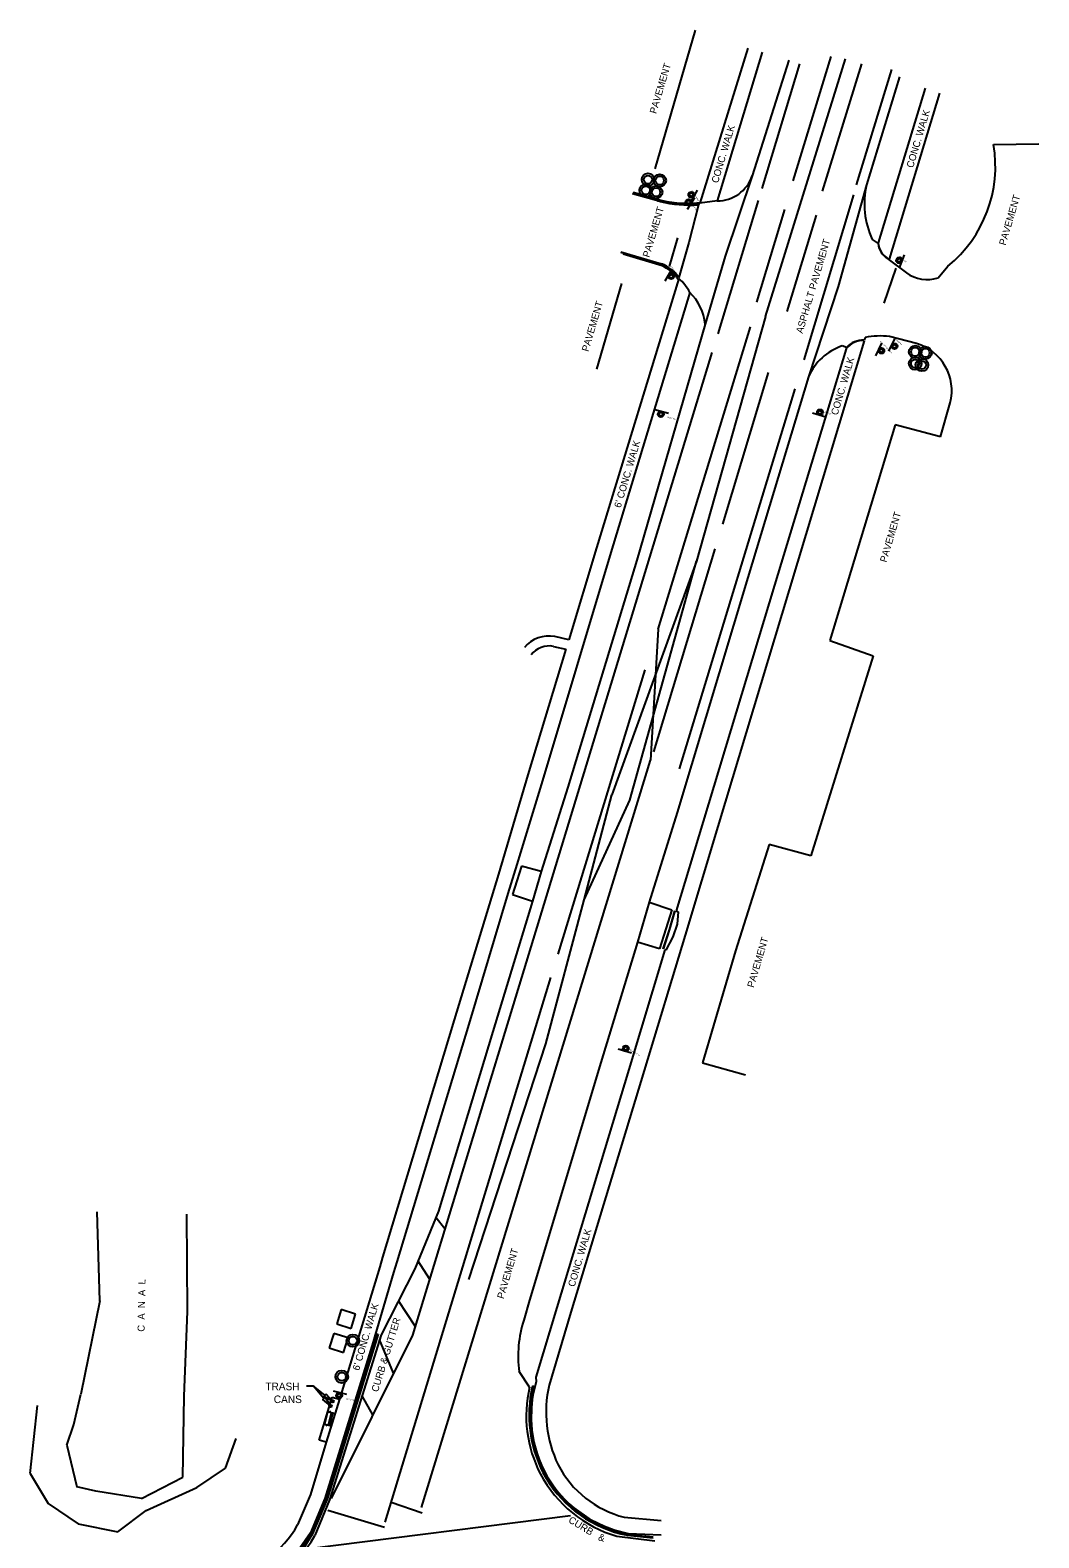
# Model space of a CAD drawing. Extents: x 925226 to 926411, y 852913 to 858733.
# Drawn here: x 925769 to 926169, y 858135 to 858733 of the extents above; entities that cross this region are included whole.
import ezdxf

# ---------------------------------------------------------------- set-up
doc = ezdxf.new("R2010")
doc.units = 0
for name, color, linetype in [('BankMent_ep', 7, 'Continuous'), ('BusStop_ep', 7, 'Continuous'), ('CGep_ep', 7, 'Continuous'), ('CGFace_ep', 7, 'Continuous'), ('CLConst_dp', 7, 'Continuous'), ('ConcSlabs_ep', 7, 'Continuous'), ('CurbRamp_ep', 7, 'Continuous'), ('EndTreat_ep', 7, 'Continuous'), ('ManholeSW_ep', 7, 'Continuous'), ('PavtAsphalt_ep', 7, 'Continuous'), ('PavtCrown_ep', 7, 'Continuous'), ('PavtMisc_ep', 7, 'Continuous'), ('SidewalkBack_ep', 7, 'Continuous'), ('SidewalkFront_ep', 7, 'Continuous'), ('TextLabel', 7, 'Continuous'), ('TextNotes', 7, 'Continuous'), ('Trash_ep', 7, 'Continuous'), ('WaterEdge_ep', 7, 'Continuous'), ('XSPt_ep', 7, 'Continuous')]:
    doc.layers.add(name, color=color, linetype=linetype)

# ---------------------------------------------------------------- blocks, each defined once
blk = doc.blocks.new('BNCH')
at = {"layer": 'BusStop_ep'}
for p, q in [((-2.5, 0), (2.5, 0)), ((-2.5, -0.5), (-2.5, -1.23)), ((2.5, -1.23), (2.5, -0.5))]:
    blk.add_line(p, q, dxfattribs=at)
blk.add_lwpolyline([(-2.5, -0.5), (2.5, -0.5), (2.5, 1.68), (-2.5, 1.68), (-2.5, 0), (-2.5, -0.5)], close=True, dxfattribs=at)
for centre, start, end in [((-3.55, 0), 0.23588, 69.15443), ((3.55, 0), 110.84558, 179.76412)]:
    blk.add_arc(centre, 1.05, start, end, dxfattribs=at)
blk = doc.blocks.new('SSS')
at = {"layer": 'ManholeSW_ep'}
blk.add_line((-2.77, 1.15), (2.77, 1.15), dxfattribs=at)
for radius in [1.15, 0.692]:
    blk.add_circle((0, 0), radius, dxfattribs=at)
blk = doc.blocks.new('BOL')
at = {"layer": 'TextNotes'}
for radius in [2.5, 1.67]:
    blk.add_circle((0, 0), radius, dxfattribs=at)

msp = doc.modelspace()

# ---------------------------------------------------------------- linework, layer by layer
at = {"layer": 'BankMent_ep'}
for p, q in [((925768.95, 858160.47), (925771.85, 858187.46)), ((925846.44, 858162.53), (925850.59, 858174.27)), ((925835.09, 858154.86), (925846.44, 858162.53)), ((925768.95, 858160.47), (925776.1, 858148.55)), ((925814.99, 858145.82), (925835.09, 858154.86)), ((925776.1, 858148.55), (925787.96, 858140.47)), ((925803.77, 858137.35), (925814.99, 858145.82)), ((925787.96, 858140.47), (925803.77, 858137.35))]:
    msp.add_line(p, q, dxfattribs=at)
at = {"layer": 'CGep_ep'}
for p, q in [((926024.35, 858383.59), (926022.22, 858375.97)), ((926022.22, 858375.97), (926019.83, 858368.44)), ((925906.86, 858215.73), (925886.63, 858150.3)), ((925886.63, 858150.3), (925880.88, 858136.47)), ((925880.88, 858136.47), (925877.28, 858130.67)), ((926003.07, 858136.54), (926005.77, 858136)), ((926005.77, 858136), (926015.98, 858134.99))]:
    msp.add_line(p, q, dxfattribs=at)
for centre, major_axis, ratio, start_param, end_param in [((926016.84, 858183.64), (-13.65, -48.2), 0.999607, 4.763001, 5.460335), ((926014.98, 858183.35), (-4.42, -48.1), 0.999813, 5.288393, 6.125776)]:
    msp.add_ellipse(centre, major_axis=major_axis, ratio=ratio, start_param=start_param, end_param=end_param, dxfattribs=at)
at = {"layer": 'CGFace_ep'}
for p, q in [((926017.66, 858665.05), (926007.77, 858667.92)), ((926033.98, 858663.72), (926033.27, 858663.71)), ((926033.98, 858663.72), (926034.34, 858664.12)), ((926003.18, 858644.71), (926019.63, 858639.83)), ((926022.42, 858375.91), (926024.72, 858383.54)), ((926020.05, 858368.38), (926022.42, 858375.91)), ((925905.43, 858212.32), (925886.23, 858150.33)), ((925906.51, 858215.66), (925905.43, 858212.32)), ((925968.46, 858195.01), (925967.93, 858192.55)), ((925886.23, 858150.33), (925880.51, 858136.71)), ((925880.51, 858136.71), (925876.45, 858130.76)), ((926015.89, 858135.26), (926005.79, 858136.12))]:
    msp.add_line(p, q, dxfattribs=at)
for centre, major_axis, ratio, start_param, end_param in [((926029.76, 858716.5), (53.9, -7.88), 0.969953, 4.629197, 4.91788), ((926013.51, 858626.08), (-14.74, 4.01), 0.984765, 4.006354, 4.561623), ((926017.13, 858183.61), (-12.56, -48.42), 0.999645, 4.786285, 5.43341), ((926015.97, 858183.98), (-38.66, -30.36), 0.999885, 6.102191, 6.664596)]:
    msp.add_ellipse(centre, major_axis=major_axis, ratio=ratio, start_param=start_param, end_param=end_param, dxfattribs=at)
at = {"layer": 'ConcSlabs_ep'}
for p, q in [((925892.24, 858225.45), (925890.52, 858219.79)), ((925897.94, 858223.61), (925892.24, 858225.45)), ((925896.16, 858217.89), (925897.94, 858223.61)), ((925889.35, 858215.97), (925887.52, 858210.25)), ((925895.06, 858214.17), (925889.35, 858215.97)), ((925890.52, 858219.79), (925896.16, 858217.89)), ((925887.52, 858210.25), (925893.21, 858208.4)), ((925893.21, 858208.4), (925895.06, 858214.17)), ((925883.48, 858173.69), (925888.66, 858190.76)), ((925888.66, 858190.76), (925891.54, 858189.9)), ((925886.3, 858172.87), (925883.48, 858173.69))]:
    msp.add_line(p, q, dxfattribs=at)
at = {"layer": 'CurbRamp_ep'}
for p, q in [((925996.42, 858138.84), (925991.39, 858141.41)), ((925996.6, 858139.38), (925991.41, 858141.95)), ((926000.34, 858137.37), (925996.42, 858138.84)), ((926000.43, 858137.97), (925996.6, 858139.38)), ((926005.79, 858136.12), (926000.34, 858137.37)), ((926006.1, 858136.53), (926000.43, 858137.97))]:
    msp.add_line(p, q, dxfattribs=at)
at = {"layer": 'EndTreat_ep'}
for p, q in [((926073.91, 858719.32), (926059.01, 858669.89)), ((926086.39, 858722.22), (926071.36, 858672.96)), ((926098.59, 858719.41), (926082.93, 858668.86)), ((926110.43, 858717.15), (926096.45, 858671.42)), ((926057.59, 858665.19), (926041.51, 858612.34)), ((926095.3, 858667.36), (926075.66, 858602.06)), ((926068.04, 858661.6), (926056.94, 858624.86)), ((926080.58, 858659.36), (926068.89, 858621.19)), ((926025.57, 858650.34), (926022.34, 858638.98)), ((926107.51, 858624.48), (926112.23, 858638.41)), ((926017.97, 858495.22), (926054.48, 858615.07)), ((926039.17, 858604.9), (925964.66, 858360.2)), ((926061.57, 858597.03), (926043.39, 858536.8)), ((926072.12, 858590.54), (926026.29, 858439.78)), ((926040.38, 858527.03), (926016.1, 858446.56)), ((926017.97, 858495.22), (926014.82, 858443.32)), ((926012.57, 858479.05), (925978.18, 858366.38)), ((925924.04, 858146.9), (926014.82, 858443.32)), ((925964.66, 858360.2), (925920.52, 858215.34)), ((925975.27, 858357.15), (925909.61, 858141.17)), ((925933.34, 858257.42), (925929.81, 858261.98)), ((925927.31, 858237.63), (925922.72, 858244.64)), ((925921.61, 858218.9), (925915, 858228.94)), ((925920.52, 858215.34), (925888.32, 858150.52)), ((925913.04, 858200.27), (925907.48, 858213.57)), ((925904.84, 858183.76), (925900.54, 858191.28)), ((925909.4, 858139.01), (925886.92, 858145.75)), ((925924.38, 858144.73), (925912.02, 858148.94)), ((925983.15, 858143.63), (925878.67, 858130.44))]:
    msp.add_line(p, q, dxfattribs=at)
at = {"layer": 'PavtAsphalt_ep'}
for p, q in [((926069.74, 858720.84), (926055.16, 858674.97)), ((926113.62, 858714.18), (926100.47, 858671.42)), ((926055.16, 858674.97), (926044.44, 858643.13)), ((926100.47, 858671.42), (926089.3, 858631.05)), ((926044.44, 858643.13), (926036.53, 858616.14)), ((926089.3, 858631.05), (926077.51, 858595.26)), ((926036.53, 858616.14), (926009.45, 858522.57)), ((926077.51, 858595.26), (926053.51, 858515.65)), ((926009.45, 858522.57), (925982.12, 858432.5)), ((926053.51, 858515.65), (926025.43, 858422.5)), ((925982.12, 858432.5), (925971.51, 858399.12)), ((926025.43, 858422.5), (926014.41, 858386.99)), ((925971.51, 858399.12), (925968.06, 858387.43)), ((925968.06, 858387.43), (925952.43, 858335.69)), ((926014.41, 858386.99), (926009.67, 858371.17)), ((926009.67, 858371.17), (925995.14, 858323.42)), ((925952.43, 858335.69), (925930.82, 858264.45)), ((925995.14, 858323.42), (925966.94, 858229.14)), ((925930.82, 858264.45), (925921.46, 858241.53)), ((925921.46, 858241.53), (925908.05, 858215.38)), ((925966.94, 858229.14), (925964.65, 858221.24)), ((925908.05, 858215.38), (925887.68, 858149.96)), ((925966.91, 858194.65), (925962.78, 858200.84)), ((925887.68, 858149.96), (925881.84, 858135.81)), ((926001.59, 858135.59), (926016.58, 858133.78))]:
    msp.add_line(p, q, dxfattribs=at)
for centre, major_axis, ratio, start_param, end_param in [((926009.4, 858206.86), (-9.08, -46.17), 0.998912, 4.5957, 5.034579), ((926015.56, 858183.31), (-12.34, -48.43), 0.999593, 4.732875, 5.442276), ((926015.54, 858183.76), (32.89, 37.87), 0.999869, 2.774585, 3.574821), ((925840.63, 858159.33), (46.88, 7.33), 0.999985, 4.643805, 5.609384)]:
    msp.add_ellipse(centre, major_axis=major_axis, ratio=ratio, start_param=start_param, end_param=end_param, dxfattribs=at)
at = {"layer": 'PavtCrown_ep'}
for p, q in [((926060.53, 858619.22), (926092.17, 858721.3)), ((926060.53, 858619.22), (926033.16, 858522.15)), ((926033.16, 858522.15), (925999.61, 858429.51)), ((926006.74, 858427.41), (926033.16, 858522.15)), ((925988.53, 858387.92), (925999.61, 858429.51)), ((925988.53, 858387.92), (926006.74, 858427.41)), ((925973.39, 858330.74), (925988.53, 858387.92)), ((925942.86, 858237.31), (925973.39, 858330.74))]:
    msp.add_line(p, q, dxfattribs=at)
at = {"layer": 'PavtMisc_ep'}
for p, q in [((926032.58, 858732.72), (926016.61, 858677.78)), ((926150.9, 858687.32), (926168.83, 858687.67)), ((926018.68, 858664.72), (926007.71, 858667.8)), ((926041.33, 858664.98), (926034.47, 858664.17)), ((926033.88, 858663.46), (926030.03, 858648.52)), ((926034.47, 858664.17), (926033.88, 858663.46)), ((926030.03, 858648.52), (926026.14, 858634.58)), ((926102.81, 858649.73), (926105.09, 858648.06)), ((926003.1, 858644.85), (926019.2, 858640.09)), ((926109.12, 858641.92), (926116.31, 858636.49)), ((926128.86, 858634.49), (926132.8, 858639.15)), ((926003.44, 858632.2), (925993.49, 858598.28)), ((926100.01, 858610.83), (926099.53, 858609.77)), ((926120.35, 858608.5), (926109.61, 858611.21)), ((926092.55, 858606.92), (926090.88, 858607.54)), ((926129.78, 858571.52), (926133.74, 858584.94)), ((926111.88, 858576.2), (926085.96, 858490.66)), ((926129.78, 858571.52), (926111.88, 858576.2)), ((926085.96, 858490.66), (926103.11, 858484.62)), ((926103.11, 858484.62), (926078.43, 858405.36)), ((926061.87, 858409.87), (926048.55, 858367.62)), ((926078.43, 858405.36), (926061.87, 858409.87)), ((925963.7, 858401.3), (925961.94, 858395.46)), ((925971.51, 858399.12), (925963.7, 858401.3)), ((925961.94, 858395.46), (925960.2, 858390)), ((925960.2, 858390), (925968.06, 858387.43)), ((926014.41, 858386.99), (926023.3, 858383.89)), ((926023.3, 858383.89), (926021.01, 858376.36)), ((926021.01, 858376.36), (926018.44, 858368.45)), ((926018.44, 858368.45), (926009.67, 858371.17)), ((926048.55, 858367.62), (926035.52, 858323.32)), ((926035.52, 858323.32), (926052.52, 858318.49))]:
    msp.add_line(p, q, dxfattribs=at)
for centre, major_axis, ratio, start_param, end_param in [((926100.59, 858678.73), (21.68, 46.23), 0.999043, 4.2635, 5.319649), ((926041.31, 858679.59), (-6.93, -12.86), 0.999654, 0.495606, 1.74275), ((926133.68, 858664.04), (-1.45, -34.02), 0.999265, 4.536192, 5.18855), ((926030.11, 858713.2), (50.89, -7.76), 0.967364, 4.634829, 4.932324), ((926113.15, 858648.94), (-5.43, 6.06), 0.994499, 0.950964, 1.888021), ((926013.96, 858626.35), (-2.51, -14.49), 0.999582, 2.336296, 2.948722), ((926124.6, 858648.32), (-12.26, 7.71), 0.997119, 1.521594, 2.430162), ((926014.87, 858620.93), (16.59, 5.22), 0.999644, 0.157336, 0.565845), ((926016.86, 858614.33), (-2.74, 19.58), 0.998961, 4.66553, 5.386333), ((926105.93, 858584.16), (-27.16, 4.18), 0.993258, 4.729873, 5.081436), ((926098, 858586.35), (-13.63, -17.74), 0.998508, 4.121326, 4.956707), ((926099.05, 858601.02), (8.58, 2.08), 0.991412, 1.279937, 2.162751), ((926114.63, 858589.66), (11.3, 16.12), 0.999648, 5.081373, 6.600063)]:
    msp.add_ellipse(centre, major_axis=major_axis, ratio=ratio, start_param=start_param, end_param=end_param, dxfattribs=at)
at = {"layer": 'SidewalkBack_ep'}
for p, q in [((926053.43, 858725.58), (926034.47, 858664.17)), ((926129.5, 858707.7), (926109.45, 858641.89)), ((926026.08, 858634.23), (925993.48, 858527.46)), ((926099.64, 858609.58), (926069.79, 858510.82)), ((925993.48, 858527.46), (925982.5, 858490.95)), ((926069.79, 858510.82), (926041.56, 858416.99)), ((925982.5, 858490.95), (925976.91, 858492.28)), ((925981.34, 858487.24), (925966.22, 858437.44)), ((925966.22, 858437.44), (925954.57, 858398.11)), ((926041.56, 858416.99), (926028.65, 858373.82)), ((925954.57, 858398.11), (925937.02, 858340.3)), ((926028.65, 858373.82), (926012.34, 858320.26)), ((925937.02, 858340.3), (925910.33, 858251.85)), ((926012.34, 858320.26), (925983.35, 858224.35)), ((925910.33, 858251.85), (925908.64, 858246.2)), ((925908.64, 858246.2), (925907.52, 858242.41)), ((925907.52, 858242.41), (925891.54, 858189.9)), ((925983.35, 858224.35), (925974.66, 858195.48)), ((925891.54, 858189.9), (925886.3, 858172.87)), ((925886.3, 858172.87), (925880.07, 858152.1)), ((925880.07, 858152.1), (925874.97, 858140.08)), ((926004.45, 858143.1), (926019.08, 858141.77))]:
    msp.add_line(p, q, dxfattribs=at)
for centre, major_axis, ratio, start_param, end_param in [((925974.5, 858480.01), (6.88, 10.45), 0.996548, 0.388905, 1.465009), ((926022.1, 858184.86), (35.68, -33.03), 0.999776, 3.668413, 4.334005), ((926014.46, 858182.6), (-40.05, -7.56), 0.999727, 0.289626, 1.135998), ((925841.12, 858158.75), (36.57, -12.52), 0.999994, 5.196605, 6.108925)]:
    msp.add_ellipse(centre, major_axis=major_axis, ratio=ratio, start_param=start_param, end_param=end_param, dxfattribs=at)
at = {"layer": 'SidewalkFront_ep'}
for p, q in [((926059.19, 858723.94), (926041.33, 858664.98)), ((926123.81, 858709.66), (926105.13, 858648.37)), ((926030.44, 858628.69), (925999.2, 858525.61)), ((926092.47, 858606.4), (926064.02, 858512.64)), ((925999.2, 858525.61), (925972.01, 858435.19)), ((926064.02, 858512.64), (926035.82, 858418.96)), ((925976.41, 858488.37), (925981.34, 858487.24)), ((925972.01, 858435.19), (925961.87, 858401.96)), ((926035.82, 858418.96), (926025.06, 858383.53)), ((925961.87, 858401.96), (925958.3, 858390.35)), ((925958.3, 858390.35), (925942.86, 858338.65)), ((926025.06, 858383.53), (926025.86, 858383.2)), ((926025.39, 858378.23), (926023.79, 858373.28)), ((926025.86, 858383.2), (926025.39, 858378.23)), ((926023.79, 858373.28), (926020.99, 858367.98)), ((926020.54, 858368.11), (926006.23, 858320.61)), ((926020.99, 858367.98), (926020.54, 858368.11)), ((925942.86, 858338.65), (925914.31, 858244.35)), ((926006.23, 858320.61), (925977.73, 858226.3)), ((925912.97, 858240.15), (925905.76, 858215.39)), ((925914.31, 858244.35), (925912.97, 858240.15)), ((925977.73, 858226.3), (925969.4, 858198.61)), ((925969.4, 858198.61), (925969.55, 858196.89)), ((925969.55, 858196.89), (925968.26, 858191.51))]:
    msp.add_line(p, q, dxfattribs=at)
for centre, major_axis, ratio, start_param, end_param in [((926113.43, 858649.23), (0.47, 8.33), 0.999665, 1.729696, 2.700159), ((926098.87, 858601.62), (5.49, 5.81), 0.999678, 0.660886, 1.687377), ((925974.57, 858479.79), (4.52, 7.53), 0.994998, 0.331219, 1.474283)]:
    msp.add_ellipse(centre, major_axis=major_axis, ratio=ratio, start_param=start_param, end_param=end_param, dxfattribs=at)
at = {"layer": 'TextLabel'}
for points in [[(925881.25, 858195.05), (925878.44, 858195.05)], [(925885.42, 858190.24), (925881.25, 858195.05)], [(925885.72, 858191.55), (925881.25, 858195.05)]]:
    msp.add_lwpolyline(points, dxfattribs=at)
for points in [[(925886.13, 858192.07), (925888.87, 858189.08), (925885.31, 858191.02)], [(925885.93, 858190.68), (925888.05, 858187.22), (925884.92, 858189.8)]]:
    msp.add_lwpolyline(points, close=True, dxfattribs=at)
at = {"layer": 'Trash_ep'}
for centre in [(925888, 858187.18), (925888.88, 858189.06)]:
    msp.add_circle(centre, 0.5, dxfattribs=at)
at = {"layer": 'WaterEdge_ep'}
for p, q in [((925796.51, 858228.84), (925795.46, 858264.15)), ((925831.29, 858224.65), (925831.03, 858263.22)), ((925796.51, 858228.84), (925789.06, 858191.89)), ((925830.03, 858191.09), (925831.29, 858224.65)), ((925786.31, 858179.85), (925789.06, 858191.89)), ((925829.51, 858159.03), (925830.03, 858191.09)), ((925783.51, 858171.72), (925786.31, 858179.85)), ((925783.51, 858171.72), (925787.5, 858155.15)), ((925813.04, 858150.55), (925829.51, 858159.03)), ((925794.95, 858153.48), (925787.5, 858155.15)), ((925813.04, 858150.55), (925794.95, 858153.48))]:
    msp.add_line(p, q, dxfattribs=at)
at = {"layer": 'XSPt_ep'}
for p, q in [((926017.55, 858665.65), (926007.94, 858668.39)), ((926034.34, 858664.12), (926033.19, 858664.2)), ((926019.47, 858639.22), (926004.07, 858643.83)), ((926025.19, 858634.79), (926025.88, 858634)), ((925904.95, 858212.64), (925885.81, 858150.48)), ((925905.76, 858215.39), (925904.95, 858212.64)), ((925905.76, 858215.39), (925906.51, 858215.66)), ((925906.51, 858215.66), (925906.86, 858215.73)), ((925968.46, 858195.01), (925968.03, 858194.83)), ((925968.91, 858194.86), (925968.46, 858195.01)), ((925968.91, 858194.86), (925968.5, 858192.97)), ((925885.81, 858150.48), (925880.04, 858136.89)), ((925984.49, 858146.8), (925991.41, 858141.95)), ((925880.04, 858136.89), (925875.92, 858130.82)), ((926019.16, 858135.94), (926006.1, 858136.53))]:
    msp.add_line(p, q, dxfattribs=at)
for centre, major_axis, ratio, start_param, end_param in [((926029.57, 858712.01), (47.98, -8.81), 0.981609, 4.641404, 4.964949), ((926014.28, 858626.59), (-6.24, -12.14), 0.999408, 2.68991, 3.226683), ((926026.31, 858182.75), (-18.92, 55.58), 0.999798, 1.06772, 1.290175), ((926015.08, 858183.16), (32.9, 34.3), 0.999871, 2.402629, 3.206579)]:
    msp.add_ellipse(centre, major_axis=major_axis, ratio=ratio, start_param=start_param, end_param=end_param, dxfattribs=at)

# ---------------------------------------------------------------- block references
at = {"layer": 'BusStop_ep', "rotation": 76.52508814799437}
msp.add_blockref('BNCH', (925887.83, 858182.01), dxfattribs=at)
at = {"layer": 'ManholeSW_ep'}
for p, rotation in [((926031.06, 858667.47), -119.92167697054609), ((926029.93, 858664.54), -122.31423539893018), ((926113.42, 858641.45), -110.7050364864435), ((926023.06, 858635.12), 60.47017666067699), ((926106.41, 858605.6), 63.439516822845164), ((926111.6, 858607.38), 64.32558220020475), ((926019, 858580.48), -14.35107947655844), ((926082.06, 858581.19), 162.6338358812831), ((926005.04, 858328.99), 162.96890728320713), ((925891.43, 858191.42), -13.723034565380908)]:
    msp.add_blockref('SSS', p, dxfattribs=dict(at, rotation=rotation))
at = {"layer": 'TextNotes'}
for p in [(926013.01, 858669.23), (926013.88, 858673.45), (926017.09, 858668.48), (926018.54, 858673.1), (926119.84, 858605.16), (926123.86, 858604.78), (926119.82, 858600.5), (926122.49, 858599.96), (925896.92, 858213.1), (925892.46, 858198.81)]:
    msp.add_blockref('BOL', p, dxfattribs=at)

# ---------------------------------------------------------------- texts
at = {"layer": 'CLConst_dp'}
for s, rotation, p in [('PARKING WARNING', 298.93345, (926029.97, 858666.29)), ('TOW WARNING', 302.06533, (926031.09, 858669.15)), ('STOP SIGN', 316.88015, (926113.46, 858642.93)), ('STOP SIGN', 306.56637, (926022.73, 858638.9)), ('TOW WARNING', 318.40008, (926110.68, 858611.02)), ('PARKING WARNING', 314.10144, (926105.78, 858609.23)), ('BUS STOP', 342.63384, (926083.15, 858581.25)), ('BUS STOP', 345.64892, (926021.59, 858579.02)), ('SPEED LIMIT 40', 326.74017, (926005.97, 858328.74)), ('BUS STOP', 346.27697, (925894.03, 858189.95))]:
    msp.add_text(s, height=0.5, rotation=rotation, dxfattribs=at).set_placement(p)
at = {"layer": 'TextLabel'}
for s, rotation, p in [('PAVEMENT', 73.49741, (926017.14, 858699.35)), ('CONC. WALK', 73.49741, (926118.96, 858677.9)), ('CONC. WALK', 73.49741, (926041.64, 858671.85)), ('PAVEMENT', 73.49741, (926155.64, 858647.18)), ('PAVEMENT', 73.49741, (926014.39, 858642.4)), ('ASPHALT PAVEMENT', 73.49741, (926075.15, 858612.26)), ('PAVEMENT', 73.49741, (925990.22, 858605.04)), ('CONC. WALK', 73.49741, (926089.01, 858579.83)), ("6' CONC. WALK", 73.49741, (926003.04, 858543.11)), ('PAVEMENT', 73.49741, (926108.42, 858521.49)), ('PAVEMENT', 73.49741, (926055.8, 858352.86)), ('CONC. WALK', 73.49741, (925984.76, 858234.23)), ('PAVEMENT', 73.49741, (925956.66, 858229.48)), ('C  A  N  A  L', 88.96696, (925814.31, 858216.64)), ("6' CONC. WALK", 73.49741, (925899.33, 858201.03)), ('CURB & GUTTER', 72.81541, (925906.81, 858192.54)), ('CURB ', 328.56901, (925982.07, 858141.26)), ('&', 346.24913, (925993.96, 858133.97))]:
    msp.add_text(s, height=2.8, rotation=rotation, dxfattribs=at).set_placement(p)
for s, p in [('TRASH', (925862.17, 858193.46)), ('CANS', (925865.53, 858188.36))]:
    msp.add_text(s, height=3, dxfattribs=at).set_placement(p)

doc.saveas('drawing.dxf')
